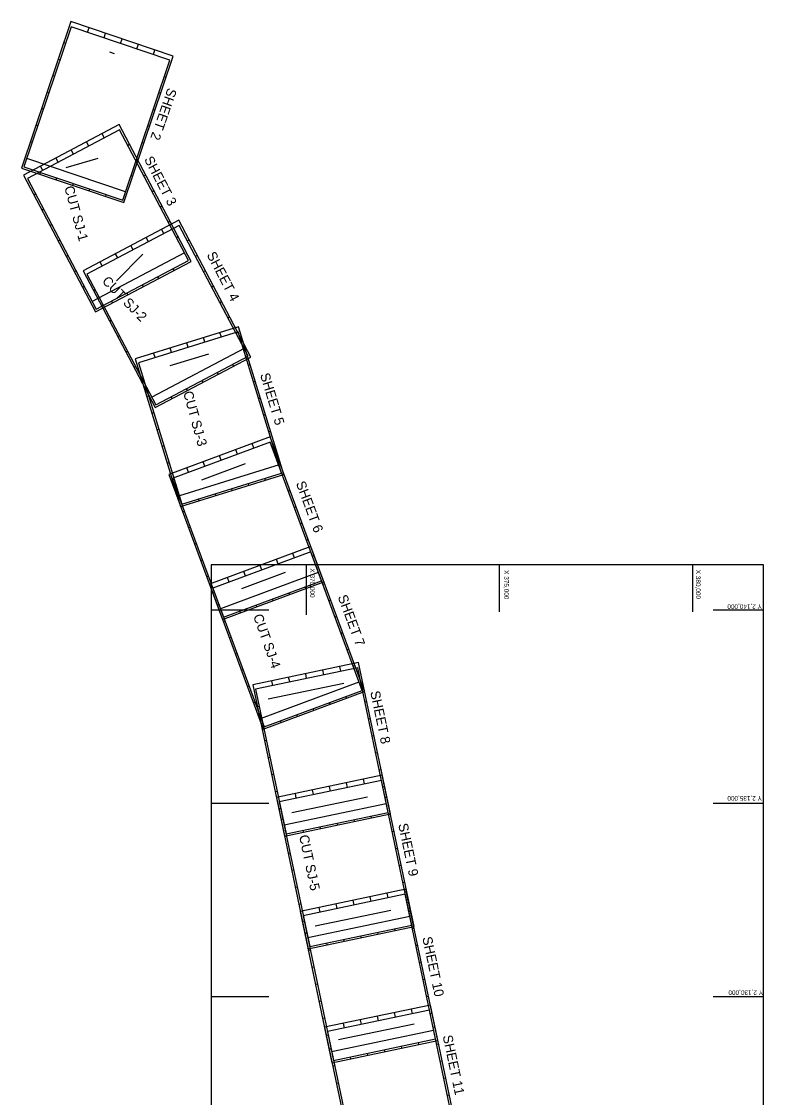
# Model space of a CAD drawing. Extents: x 518852 to 589310, y 1937169 to 2155394.
# Drawn here: x 518852 to 538065, y 2127557 to 2155394 of the extents above; entities that cross this region are included whole.
import ezdxf

# ---------------------------------------------------------------- set-up
doc = ezdxf.new("R2010")
doc.units = 0
for name, color, linetype in [('Level 1', 7, 'Continuous'), ('Level 2', 7, 'Continuous'), ('Level 3', 7, 'Continuous'), ('Level 58', 7, 'Continuous')]:
    doc.layers.add(name, color=color, linetype=linetype)

msp = doc.modelspace()

# ---------------------------------------------------------------- linework, layer by layer
at = {"layer": 'Level 1'}
for p, q in [((520562, 2155116), (520602, 2155235)), ((519945, 2154849), (519992, 2154833)), ((520989, 2154972), (521029, 2155091)), ((521415, 2154829), (521455, 2154947)), ((521842, 2154685), (521882, 2154804)), ((522268, 2154542), (522308, 2154660)), ((519801, 2154423), (519849, 2154407)), ((519658, 2153996), (519705, 2153980)), ((522551, 2153972), (522599, 2153956)), ((519514, 2153570), (519562, 2153554)), ((522408, 2153545), (522455, 2153529)), ((519371, 2153143), (519418, 2153127)), ((522264, 2153119), (522312, 2153103)), ((519227, 2152717), (519275, 2152701)), ((522121, 2152692), (522168, 2152676)), ((520995, 2152383), (520937, 2152493)), ((519084, 2152290), (519131, 2152274)), ((520199, 2151963), (520140, 2152073)), ((520597, 2152173), (520538, 2152283)), ((521603, 2152194), (521647, 2152218)), ((521977, 2152266), (522024, 2152250)), ((521546, 2150986), (518987, 2151848)), ((519801, 2151753), (519742, 2151864)), ((521813, 2151796), (521857, 2151820)), ((521833, 2151839), (521881, 2151823)), ((519403, 2151543), (519344, 2151654)), ((519326, 2151444), (519342, 2151491)), ((519753, 2151300), (519769, 2151347)), ((521690, 2151413), (521737, 2151397)), ((522023, 2151398), (522067, 2151422)), ((520179, 2151156), (520195, 2151204)), ((520606, 2151013), (520622, 2151060)), ((522232, 2151000), (522277, 2151024)), ((519170, 2150912), (519214, 2150935)), ((521032, 2150869), (521048, 2150917)), ((519380, 2150514), (519424, 2150537)), ((522442, 2150602), (522487, 2150626)), ((519590, 2150116), (519634, 2150139)), ((522652, 2150204), (522696, 2150227)), ((522538, 2149907), (522479, 2150018)), ((522862, 2149806), (522906, 2149829)), ((519800, 2149718), (519844, 2149741)), ((521742, 2149487), (521683, 2149598)), ((522140, 2149697), (522081, 2149808)), ((523146, 2149719), (523190, 2149742)), ((520010, 2149320), (520054, 2149343)), ((523072, 2149408), (520684, 2148149)), ((521344, 2149277), (521285, 2149388)), ((523355, 2149321), (523400, 2149344)), ((520945, 2149068), (520887, 2149178)), ((522802, 2148955), (522779, 2148999)), ((520220, 2148922), (520264, 2148945)), ((522404, 2148745), (522381, 2148789)), ((523565, 2148923), (523610, 2148946)), ((520429, 2148524), (520474, 2148547)), ((520713, 2148436), (520757, 2148460)), ((522006, 2148535), (521983, 2148579)), ((523775, 2148525), (523819, 2148548)), ((521210, 2148115), (521187, 2148160)), ((521608, 2148325), (521585, 2148369)), ((520923, 2148038), (520967, 2148062)), ((523985, 2148127), (524029, 2148150)), ((521133, 2147640), (521177, 2147664)), ((524195, 2147729), (524239, 2147752)), ((524029, 2147230), (523992, 2147349)), ((524405, 2147331), (524449, 2147354)), ((521343, 2147242), (521387, 2147265)), ((523169, 2146964), (523132, 2147084)), ((523599, 2147097), (523562, 2147217)), ((521553, 2146844), (521597, 2146867)), ((524615, 2146933), (522226, 2145673)), ((522309, 2146699), (522272, 2146819)), ((522739, 2146832), (522702, 2146951)), ((524591, 2146932), (524639, 2146947)), ((524345, 2146479), (524322, 2146524)), ((524724, 2146502), (524772, 2146517)), ((521762, 2146446), (521807, 2146469)), ((523947, 2146270), (523924, 2146314)), ((521964, 2146122), (522011, 2146137)), ((521972, 2146048), (522017, 2146071)), ((523549, 2146060), (523526, 2146104)), ((524857, 2146072), (524904, 2146087)), ((522096, 2145692), (522144, 2145707)), ((522753, 2145640), (522729, 2145684)), ((523151, 2145850), (523127, 2145894)), ((524989, 2145642), (525037, 2145657)), ((522229, 2145262), (522277, 2145277)), ((525122, 2145212), (525170, 2145227)), ((522361, 2144832), (522409, 2144847)), ((525255, 2144782), (525302, 2144797)), ((522494, 2144402), (522542, 2144417)), ((524444, 2144199), (524401, 2144317)), ((524866, 2144356), (524823, 2144473)), ((525387, 2144352), (525435, 2144367)), ((522627, 2143972), (522674, 2143987)), ((523600, 2143887), (523557, 2144004)), ((524022, 2144043), (523979, 2144160)), ((525444, 2144090), (525491, 2144107)), ((525520, 2143922), (522940, 2143126)), ((523178, 2143731), (523135, 2143848)), ((522759, 2143542), (522807, 2143557)), ((524741, 2143394), (524726, 2143442)), ((525171, 2143527), (525156, 2143575)), ((525601, 2143668), (525647, 2143685)), ((522865, 2143135), (522912, 2143152)), ((523881, 2143129), (523866, 2143177)), ((524311, 2143262), (524296, 2143309)), ((525757, 2143246), (525804, 2143263)), ((523451, 2142996), (523436, 2143044)), ((523022, 2142713), (523069, 2142730)), ((525913, 2142824), (525960, 2142841)), ((526069, 2142402), (526116, 2142420)), ((523178, 2142291), (523225, 2142308)), ((523334, 2141869), (523381, 2141886)), ((526226, 2141980), (526273, 2141998)), ((525496, 2141362), (525453, 2141479)), ((525918, 2141518), (525875, 2141635)), ((526382, 2141558), (526429, 2141576)), ((523491, 2141447), (523538, 2141464)), ((525074, 2141205), (525031, 2141322)), ((526496, 2141252), (526543, 2141270)), ((523647, 2141025), (523694, 2141042)), ((526538, 2141136), (524007, 2140198)), ((524230, 2140893), (524187, 2141010)), ((524652, 2141049), (524609, 2141166)), ((526212, 2140722), (526195, 2140769)), ((526653, 2140830), (526700, 2140848)), ((523803, 2140603), (523850, 2140620)), ((525368, 2140409), (525351, 2140456)), ((525790, 2140566), (525773, 2140613)), ((526809, 2140408), (526856, 2140426)), ((523918, 2140297), (523965, 2140314)), ((524524, 2140097), (524507, 2140144)), ((524946, 2140253), (524929, 2140300)), ((524074, 2139875), (524121, 2139892)), ((526965, 2139986), (527012, 2140004)), ((527122, 2139564), (527169, 2139582)), ((524230, 2139453), (524277, 2139470)), ((524387, 2139031), (524433, 2139048)), ((527278, 2139142), (527325, 2139160)), ((527117, 2138584), (527091, 2138707)), ((527434, 2138720), (527481, 2138738)), ((524543, 2138609), (524590, 2138626)), ((525796, 2138307), (525770, 2138429)), ((526236, 2138399), (526211, 2138522)), ((526677, 2138492), (526651, 2138614)), ((524699, 2138187), (524746, 2138204)), ((527591, 2138298), (525059, 2137360)), ((525356, 2138214), (525330, 2138337)), ((527650, 2138236), (527699, 2138247)), ((527264, 2137884), (527247, 2137931)), ((524856, 2137765), (524902, 2137782)), ((524959, 2137671), (525008, 2137681)), ((526420, 2137571), (526403, 2137618)), ((526842, 2137728), (526825, 2137775)), ((527742, 2137796), (527791, 2137806)), ((525576, 2137259), (525559, 2137306)), ((525998, 2137415), (525981, 2137462)), ((527835, 2137356), (527884, 2137366)), ((525051, 2137231), (525100, 2137241)), ((525144, 2136790), (525193, 2136801)), ((527928, 2136915), (527976, 2136926)), ((528020, 2136475), (528069, 2136485)), ((525236, 2136350), (525285, 2136360)), ((525329, 2135910), (525378, 2135920)), ((528113, 2136035), (528161, 2136045)), ((527290, 2135577), (527264, 2135700)), ((527730, 2135670), (527704, 2135792)), ((525421, 2135469), (525470, 2135479)), ((525968, 2135300), (525943, 2135422)), ((526409, 2135392), (526383, 2135515)), ((526849, 2135485), (526824, 2135607)), ((528205, 2135594), (528254, 2135604)), ((528298, 2135154), (525655, 2134599)), ((528263, 2135322), (528312, 2135332)), ((525514, 2135029), (525563, 2135039)), ((527914, 2134792), (527903, 2134841)), ((528355, 2134882), (528404, 2134892)), ((525572, 2134757), (525621, 2134767)), ((526593, 2134515), (526582, 2134564)), ((527033, 2134607), (527023, 2134656)), ((527473, 2134700), (527463, 2134749)), ((525664, 2134316), (525713, 2134327)), ((526152, 2134422), (526142, 2134471)), ((528448, 2134441), (528497, 2134451)), ((528540, 2134001), (528589, 2134011)), ((525757, 2133876), (525806, 2133886)), ((525849, 2133435), (525898, 2133446)), ((528633, 2133560), (528682, 2133571)), ((528725, 2133120), (528774, 2133130)), ((525942, 2132995), (525991, 2133005)), ((527463, 2132536), (527437, 2132659)), ((527904, 2132629), (527878, 2132751)), ((528344, 2132722), (528318, 2132844)), ((528818, 2132680), (528867, 2132690)), ((526034, 2132555), (526083, 2132565)), ((526582, 2132351), (526557, 2132474)), ((527023, 2132444), (526997, 2132566)), ((528877, 2132374), (528926, 2132384)), ((526127, 2132114), (526176, 2132125)), ((528911, 2132239), (526268, 2131684)), ((526186, 2131808), (526235, 2131819)), ((527646, 2131693), (527636, 2131742)), ((528086, 2131785), (528076, 2131834)), ((528527, 2131878), (528516, 2131927)), ((528969, 2131933), (529018, 2131944)), ((526765, 2131508), (526755, 2131557)), ((527206, 2131600), (527195, 2131649)), ((529062, 2131493), (529111, 2131503)), ((526278, 2131368), (526327, 2131378)), ((526371, 2130928), (526420, 2130938)), ((529154, 2131052), (529203, 2131063)), ((529247, 2130612), (529296, 2130622)), ((526463, 2130487), (526512, 2130497)), ((529339, 2130172), (529388, 2130182)), ((526556, 2130047), (526605, 2130057)), ((528979, 2129724), (528953, 2129846)), ((526648, 2129606), (526697, 2129617)), ((527658, 2129447), (527632, 2129569)), ((528098, 2129539), (528072, 2129661)), ((528539, 2129632), (528513, 2129754)), ((529432, 2129731), (529481, 2129742)), ((529524, 2129291), (526882, 2128736)), ((527217, 2129354), (527192, 2129476)), ((529512, 2129376), (529561, 2129387)), ((526741, 2129166), (526790, 2129176)), ((529141, 2128929), (529130, 2128978)), ((526821, 2128811), (526870, 2128821)), ((527819, 2128652), (527809, 2128701)), ((528260, 2128744), (528250, 2128793)), ((528700, 2128837), (528690, 2128886)), ((529604, 2128936), (529653, 2128946)), ((527379, 2128559), (527369, 2128608)), ((529697, 2128495), (529746, 2128506)), ((526913, 2128371), (526962, 2128381)), ((527006, 2127930), (527055, 2127940)), ((529789, 2128055), (529838, 2128065)), ((529882, 2127615), (529931, 2127625))]:
    msp.add_line(p, q, dxfattribs=at)
for points in [[(520128, 2155394), (518852, 2151603), (521506, 2150710), (522782, 2154501)], [(520136, 2155260), (518916, 2151635), (521475, 2150773), (522695, 2154398)], [(518902, 2151420), (520768, 2147882), (523244, 2149188), (521379, 2152726)], [(519005, 2151333), (520789, 2147950), (523177, 2149209), (521393, 2152593)], [(520445, 2148945), (522310, 2145407), (524787, 2146713), (522922, 2150251)], [(520547, 2148858), (522331, 2145474), (524720, 2146733), (522936, 2150117)], [(521794, 2146671), (522973, 2142849), (525649, 2143674), (524470, 2147496)], [(521879, 2146567), (523006, 2142911), (525586, 2143707), (524459, 2147362)], [(522666, 2143674), (524055, 2139923), (526681, 2140896), (525291, 2144647)], [(522756, 2143574), (524085, 2139987), (526617, 2140925), (525288, 2144512)], [(523718, 2140836), (525107, 2137085), (527733, 2138058), (526344, 2141809)], [(523808, 2140736), (525137, 2137149), (527669, 2138087), (526340, 2141674)], [(524841, 2138234), (525663, 2134319), (528403, 2134895), (527581, 2138809)], [(524915, 2138122), (525701, 2134378), (528344, 2134934), (527557, 2138677)], [(525453, 2135319), (526276, 2131405), (529016, 2131980), (528194, 2135895)], [(525528, 2135207), (526314, 2131464), (528957, 2132019), (528170, 2135762)], [(526067, 2132371), (526890, 2128456), (529630, 2129032), (528808, 2132947)], [(526142, 2132259), (526928, 2128516), (529571, 2129071), (528784, 2132814)], [(526702, 2129374), (527525, 2125459), (530265, 2126035), (529443, 2129949)], [(526777, 2129262), (527563, 2125518), (530206, 2126073), (529419, 2129817)]]:
    msp.add_lwpolyline(points, close=True, dxfattribs=at)
for points in [[(538065, 2141334), (523767, 2141334)], [(523767, 2141334), (523767, 2112160)], [(538065, 2104085), (538065, 2141334)]]:
    msp.add_lwpolyline(points, dxfattribs=at)
at = {"layer": 'Level 2'}
for p, q in [((526231, 2140047), (526231, 2141334)), ((531231, 2140118), (531231, 2141334)), ((536231, 2140118), (536231, 2141334)), ((523767, 2140174), (525259, 2140174)), ((536765, 2140174), (538065, 2140174)), ((523767, 2135174), (525259, 2135174)), ((536765, 2135174), (538065, 2135174)), ((523767, 2130174), (525259, 2130174)), ((536765, 2130174), (538065, 2130174))]:
    msp.add_line(p, q, dxfattribs=at)
at = {"layer": 'Level 58'}
for p, q in [((521257, 2154558), (521138, 2154598)), ((520010, 2151620), (520841, 2151856)), ((521311, 2148681), (521994, 2149372)), ((522699, 2146496), (523704, 2146793)), ((523518, 2143539), (524652, 2143958)), ((524558, 2140725), (525692, 2141144)), ((525241, 2137872), (527200, 2138277)), ((525849, 2134934), (527807, 2135339)), ((526456, 2131996), (528415, 2132401)), ((527064, 2129059), (529023, 2129464))]:
    msp.add_line(p, q, dxfattribs=at)

# ---------------------------------------------------------------- texts
at = {"layer": 'Level 3'}
for s, rotation, p in [('X 370,000', 270, (526326, 2141246)), ('X 380,000', 270, (536316, 2141210)), ('X 375,000', 270, (531351, 2141199)), ('Y 2,140,000', 180, (538023, 2140318)), ('Y 2,135,000', 180, (538023, 2135356)), ('Y 2,130,000', 180, (538052, 2130331))]:
    msp.add_text(s, height=120, rotation=rotation, dxfattribs=at).set_placement(p)
at = {"layer": 'Level 58'}
for s, rotation, p in [('SHEET 2', 250.7437, (522644, 2153695)), ('SHEET 3', 297.4934, (522021, 2151831)), ('CUT SJ-1', 285.2587, (519958, 2151104)), ('SHEET 4', 297.4934, (523641, 2149361)), ('CUT SJ-2', 314.2529, (520921, 2148660)), ('SHEET 5', 286.8687, (525026, 2146260)), ('CUT SJ-3', 285.2587, (523036, 2145797)), ('SHEET 6', 290.3291, (525954, 2143451)), ('SHEET 7', 290.3291, (527038, 2140511)), ('CUT SJ-4', 289.4543, (524847, 2140015)), ('SHEET 8', 281.8635, (527880, 2138050)), ('SHEET 9', 281.8635, (528605, 2134624)), ('CUT SJ-5', 281.8635, (526038, 2134326)), ('SHEET 10', 281.8635, (529230, 2131692)), ('SHEET 11', 281.8635, (529757, 2129147))]:
    msp.add_text(s, height=250, rotation=rotation, dxfattribs=at).set_placement(p)

doc.saveas('drawing.dxf')
